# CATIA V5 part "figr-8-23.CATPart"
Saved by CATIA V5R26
Part number: Part1
Bounding box of the stored display mesh (mm): x -50 to 50, y -62.5 to 62.5, z 0 to 10
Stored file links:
  D:\_Deepak\CATIA\CATIA V5-6R2016_Deepak\Resources\Part files\Partfiles\c08_catia_v5_6r2016_prt\figr-8-23.CATPart
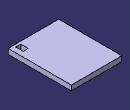
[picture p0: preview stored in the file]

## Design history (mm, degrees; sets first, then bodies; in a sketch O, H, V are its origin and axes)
Body1 (main body)
  Sketch1 on xy-plane, origin (0, 0, 0), H (1, 0, 0), V (0, 1, 0)
    line L1 (-50, 62.5) -> (50, 62.5)
    line L2 (50, 62.5) -> (50, -62.5)
    line L3 (50, -62.5) -> (-50, -62.5)
    line L4 (-50, -62.5) -> (-50, 62.5)
    axis line L5 (50, -62.5) -> (-50, 62.5)
    length L3 = 100
    length L2 = 125
    horizontal: L1 H, L3 H
    vertical: L2 V, L4 V
    midpoint: O L5
  Pad1: profile Sketch1, direction (0, 0, 1), length 10
  Sketch2 on face of Pad1, origin (0, 0, 10), H (1, 0, 0), V (0, 1, 0)
    line L1 (40, -57.5) -> (30, -57.5)
    line L2 (30, -57.5) -> (30, -42.5)
    line L3 (30, -42.5) -> (40, -42.5)
    line L4 (40, -42.5) -> (40, -57.5)
    reference projected line E1 (-50, -62.5) -> (50, -62.5) from edge [face of Pad1 | face of Pad1]
    reference projected line E2 (50, -62.5) -> (50, 62.5) from edge [face of Pad1 | face of Pad1]
    length L1 = 10
    length L4 = 15
    distance L1 E1 = 5
    distance L4 E2 = 10
    horizontal: L1 H, L3 H
    vertical: L2 V, L4 V
  Pocket1: profile Sketch2, direction (0, 0, -1), through (limit type 3)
